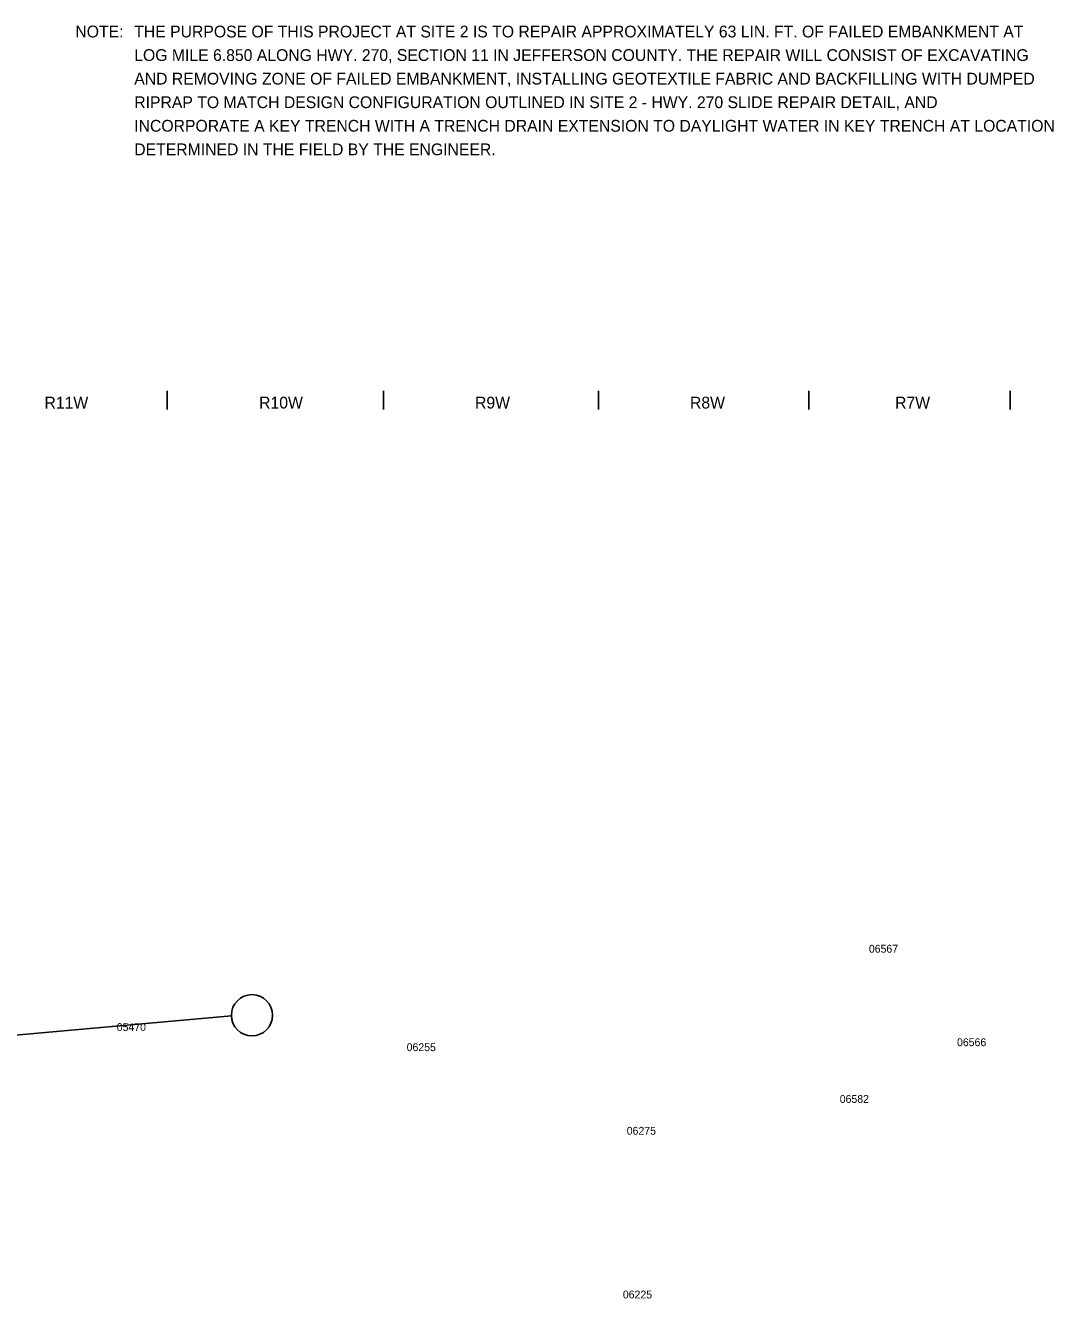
# Model space of a CAD drawing. Extents: x -42408 to 34530, y -43140 to 20491.
# Drawn here: x 6343 to 11580, y -27452 to -20969 of the extents above; entities that cross this region are included whole.
import ezdxf

# ---------------------------------------------------------------- set-up
doc = ezdxf.new("R2010")
doc.units = 0
for name, color, linetype in [('2', 7, 'Continuous'), ('30', 7, 'Continuous'), ('Default', 7, 'Continuous'), ('R_Proposed Road_Shoulder', 7, 'Continuous')]:
    doc.layers.add(name, color=color, linetype=linetype)

msp = doc.modelspace()

# ---------------------------------------------------------------- linework, layer by layer
at = {"layer": '30'}
msp.add_line((5265.6, -26204.7), (7391.4, -26011.8), dxfattribs=at)
msp.add_circle((7496.4, -26009.6), 105, dxfattribs=at)
at = {"layer": 'Default'}
for p, q in [((7063.9, -22829.2), (7063.9, -22924.2)), ((8166.7, -22829.2), (8166.7, -22924.2)), ((9261.9, -22829.2), (9261.9, -22924.2)), ((10332.7, -22829.2), (10332.7, -22924.2)), ((11359.5, -22829.2), (11359.5, -22924.2))]:
    msp.add_line(p, q, dxfattribs=at)

# ---------------------------------------------------------------- texts
at = {"layer": '2'}
for s, p in [('R11W', (6439.4, -22920)), ('R10W', (7532.9, -22920)), ('R9W', (8632.7, -22920)), ('R8W', (9727.8, -22920)), ('R7W', (10772.6, -22920))]:
    msp.add_text(s, height=60, dxfattribs=at).set_placement(p)
at = {"layer": '30'}
for s, p in [('NOTE:', (6596.7, -21030.3)), ('THE PURPOSE OF THIS PROJECT AT SITE 2 IS TO REPAIR APPROXIMATELY 63 LIN. FT. OF FAILED EMBANKMENT AT', (6896.7, -21030.3)), ('LOG MILE 6.850 ALONG HWY. 270, SECTION 11 IN JEFFERSON COUNTY. THE REPAIR WILL CONSIST OF EXCAVATING', (6896.7, -21150.3)), ('AND REMOVING ZONE OF FAILED EMBANKMENT, INSTALLING GEOTEXTILE FABRIC AND BACKFILLING WITH DUMPED', (6896.7, -21270.3)), ('RIPRAP TO MATCH DESIGN CONFIGURATION OUTLINED IN SITE 2 - HWY. 270 SLIDE REPAIR DETAIL, AND', (6896.7, -21390.3)), ('INCORPORATE A KEY TRENCH WITH A TRENCH DRAIN EXTENSION TO DAYLIGHT WATER IN KEY TRENCH AT LOCATION', (6896.7, -21510.3)), ('DETERMINED IN THE FIELD BY THE ENGINEER.', (6896.7, -21630.3))]:
    msp.add_text(s, height=60, dxfattribs=at).set_placement(p)
at = {"layer": 'R_Proposed Road_Shoulder'}
for s, p in [('06567', (10639.2, -25690.9)), ('05470', (6807.5, -26089.9)), ('06255', (8284.5, -26192.3)), ('06566', (11088.2, -26167)), ('06582', (10490.7, -26455.9)), ('06275', (9405.6, -26617.9)), ('06225', (9385.9, -27451.6))]:
    msp.add_text(s, height=40, dxfattribs=at).set_placement(p)

doc.saveas('drawing.dxf')
